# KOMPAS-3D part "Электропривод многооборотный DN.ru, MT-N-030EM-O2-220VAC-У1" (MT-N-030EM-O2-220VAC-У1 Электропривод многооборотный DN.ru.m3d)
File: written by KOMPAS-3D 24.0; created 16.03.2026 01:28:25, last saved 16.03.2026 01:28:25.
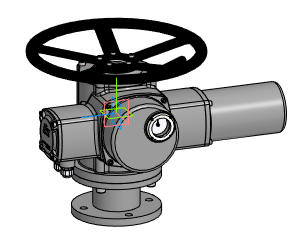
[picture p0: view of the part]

Document properties: Автор: DN.RU; Полное имя файла: D:\PROJECT CAD\DN.RU\...193.(ACTUALE) MT-N-xEM-O2-x-У1 Электропривод многооборотный DN.ru\MT-N-030EM-O2-220VAC-У1\MT-N-030EM-O2-220VAC-У1 Электропривод многооборотный DN.ru.m3d

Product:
- Body: Твердое тело1  | qty 1
    Масса: 75.278327
- Part/product: Электропривод многооборотный DN.ru  | designation MT-N-030EM-O2-220VAC-У1
    Масса: 12
    Раздел спецификации: Прочие изделия
    Комментарий: D300-04893
    Примечание: D300-04893
    additional columns: Сталь

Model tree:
1. Твердое тело1  (labels: Твердое тело1)

Expressions: MT-N-030EM-O2-220VAC-У1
